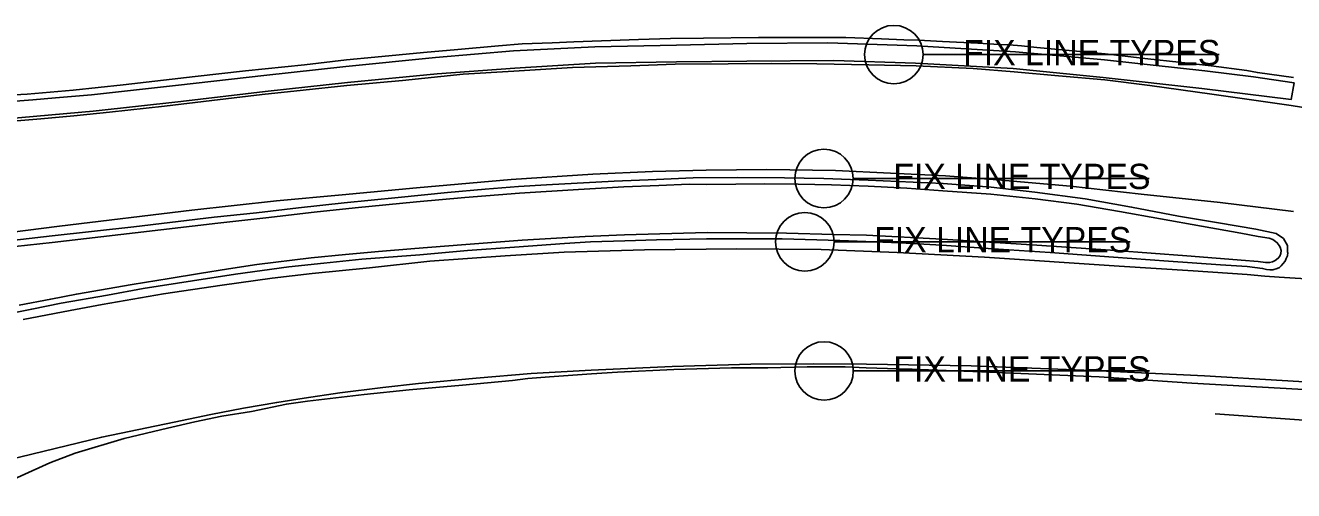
# Model space of a CAD drawing. Extents: x 1659932 to 1663108, y 619867 to 620611.
# Drawn here: x 1660072.9 to 1660213.5, y 620236 to 620287.5 of the extents above; entities that cross this region are included whole.
import ezdxf

# ---------------------------------------------------------------- set-up
doc = ezdxf.new("R2010")
doc.units = 0
for name, color, linetype in [('PM_X_CL_Double_Solid', 7, 'Continuous'), ('PM_X_Lane_Line', 7, 'Continuous'), ('PV_X_Curb', 7, 'Continuous'), ('PV_X_EOP', 7, 'Continuous'), ('RD_X_GR_Lt', 7, 'Continuous'), ('SC_Scratch6', 7, 'Continuous')]:
    doc.layers.add(name, color=color, linetype=linetype)

msp = doc.modelspace()

# ---------------------------------------------------------------- linework, layer by layer
at = {"layer": 'PM_X_CL_Double_Solid'}
msp.add_lwpolyline([(1660345.63, 620252.57), (1660326.3, 620253.2), (1660317.98, 620253.46), (1660304.58, 620253.99), (1660293.85, 620254.51), (1660282.78, 620255.07), (1660272.36, 620255.63), (1660263.03, 620256.2), (1660252.35, 620256.91), (1660236.63, 620258.02), (1660227.99, 620258.63), (1660211.88, 620259.64)], dxfattribs=at)
at = {"layer": 'PM_X_Lane_Line'}
for points in [[(1660220.57, 620277.48), (1660213.23, 620278.66), (1660204.42, 620279.91), (1660197.57, 620280.86), (1660192.56, 620281.48), (1660187.43, 620281.94), (1660182.52, 620282.36), (1660177.98, 620282.73), (1660171.66, 620283.04), (1660166.4, 620283.16), (1660160.63, 620283.25), (1660155.64, 620283.31), (1660150.81, 620283.26), (1660144.95, 620283.21), (1660140.02, 620283.05), (1660133.55, 620282.84), (1660127.08, 620282.43), (1660121.44, 620282.1), (1660114.73, 620281.43), (1660108.54, 620280.86), (1660103.72, 620280.33), (1660099.18, 620279.85), (1660093.58, 620279.19), (1660088.35, 620278.57), (1660082.26, 620277.89), (1660078.29, 620277.51), (1660074.65, 620277.16), (1660071.11, 620276.87)], [(1660213.49, 620266.92), (1660205.36, 620267.91), (1660196.6, 620268.82), (1660188.78, 620269.71), (1660180.66, 620270.42), (1660174.89, 620270.87), (1660162.71, 620271.46), (1660155.11, 620271.55), (1660148.39, 620271.5), (1660142.45, 620271.33), (1660135.83, 620271.03), (1660126.77, 620270.44), (1660116.26, 620269.53), (1660108.04, 620268.76), (1660100.75, 620268.07), (1660091.39, 620267.06), (1660076.7, 620265.28), (1660067.7, 620264.15)], [(1660211.88, 620259.64), (1660210.3, 620259.74), (1660208.35, 620259.94), (1660202.36, 620260.32), (1660194.17, 620260.83), (1660179.22, 620261.83), (1660169.55, 620262.37), (1660161.11, 620262.71), (1660151.78, 620262.75), (1660141.54, 620262.65), (1660132.63, 620262.4), (1660126.11, 620262.01), (1660117.74, 620261.4), (1660111.08, 620260.67), (1660104.71, 620260.03), (1660100.29, 620259.51), (1660094.72, 620258.76), (1660088.23, 620257.77), (1660081.42, 620256.6), (1660077.9, 620255.93), (1660072.69, 620254.93)], [(1660220.84, 620247.68), (1660203.63, 620248.69), (1660191.19, 620249.3), (1660177.76, 620249.8), (1660166.15, 620250.01), (1660160.33, 620250.02), (1660153.33, 620249.99), (1660144.62, 620249.74), (1660135.64, 620249.34), (1660128.98, 620248.97), (1660122.9, 620248.46), (1660116.49, 620247.86), (1660112.55, 620247.42), (1660107.77, 620246.8), (1660103.82, 620246.23), (1660100.78, 620245.75), (1660097.1, 620245.11), (1660093.49, 620244.43), (1660089.41, 620243.57), (1660081.39, 620241.92), (1660064.47, 620237.81)]]:
    msp.add_lwpolyline(points, dxfattribs=at)
at = {"layer": 'PV_X_Curb'}
for points in [[(1660213.49, 620281.76), (1660209.48, 620282.29), (1660208.29, 620282.53), (1660204.35, 620283.05), (1660200.77, 620283.43), (1660197.34, 620283.8), (1660192.61, 620284.35), (1660185.04, 620285.06), (1660183.33, 620285.24), (1660181.95, 620285.36), (1660180.85, 620285.4), (1660178.5, 620285.54), (1660174.56, 620285.73), (1660171.93, 620285.9), (1660170.3, 620285.93), (1660167.82, 620286.03), (1660163.85, 620286.17), (1660161.17, 620286.19), (1660156.01, 620286.17), (1660154.19, 620286.19), (1660148.1, 620286.11), (1660144.41, 620286.07), (1660140.88, 620285.97), (1660133.71, 620285.69), (1660131.3, 620285.6), (1660127.98, 620285.46), (1660125.37, 620285.24), (1660120.85, 620284.86), (1660117.06, 620284.52), (1660111.66, 620283.99), (1660108.51, 620283.69), (1660103.85, 620283.15), (1660097.33, 620282.49), (1660091.75, 620281.87), (1660083.77, 620280.94), (1660078.24, 620280.35), (1660073.12, 620279.9), (1660069.53, 620279.7)], [(1660213.54, 620281.17), (1660209.03, 620281.82), (1660203.65, 620282.48), (1660192.53, 620283.69), (1660182.67, 620284.6), (1660171.74, 620285.24), (1660161.86, 620285.59), (1660152.9, 620285.52), (1660145.1, 620285.33), (1660136.03, 620285.13), (1660127.04, 620284.7), (1660118.4, 620283.95), (1660108.43, 620282.98), (1660099.34, 620281.96), (1660089.91, 620280.89), (1660080.26, 620279.81), (1660076.27, 620279.49), (1660073.74, 620279.27), (1660071.83, 620279.13)], [(1660212.82, 620262.38), (1660212.81, 620263.12), (1660212.37, 620263.91), (1660211.56, 620264.48), (1660209.29, 620264.93), (1660205.16, 620265.66), (1660200.75, 620266.39), (1660195.54, 620267.39), (1660190.4, 620268.29), (1660184.82, 620269.06), (1660179.98, 620269.6), (1660174.66, 620270), (1660166.34, 620270.36), (1660161.44, 620270.56), (1660157.06, 620270.62), (1660151.83, 620270.67), (1660146.93, 620270.62), (1660142.87, 620270.46), (1660138.18, 620270.25), (1660130.69, 620269.87), (1660127.57, 620269.67), (1660123.9, 620269.36), (1660119.7, 620269.01), (1660114.24, 620268.47), (1660108.25, 620267.87), (1660103.18, 620267.32), (1660098.54, 620266.76), (1660093.86, 620266.27), (1660084.95, 620265.21), (1660075.89, 620264.19), (1660066.28, 620263.11)], [(1660072.24, 620256.54), (1660075.73, 620257.21), (1660078.59, 620257.75), (1660084.77, 620258.83), (1660088.86, 620259.5), (1660092.24, 620260.05), (1660095.45, 620260.56), (1660098.58, 620261.03), (1660104.59, 620261.76), (1660108.41, 620262.15), (1660112.06, 620262.47), (1660116.09, 620262.81), (1660121.25, 620263.22), (1660127.98, 620263.73), (1660134.98, 620264.12), (1660139.34, 620264.33), (1660148.49, 620264.59), (1660157.3, 620264.51), (1660162.5, 620264.36), (1660166.14, 620264.27), (1660174.52, 620263.84), (1660184.48, 620263.21), (1660193.76, 620262.59), (1660201.65, 620261.99), (1660208.16, 620261.48), (1660209.08, 620261.42), (1660209.55, 620261.35), (1660210.36, 620261.24), (1660210.83, 620261.25), (1660211.16, 620261.32), (1660211.46, 620261.47), (1660211.79, 620261.72), (1660211.97, 620261.96), (1660212.08, 620262.26), (1660212.1, 620262.59), (1660212, 620262.97), (1660211.89, 620263.15), (1660211.67, 620263.44), (1660211.5, 620263.57), (1660211.18, 620263.79), (1660210.79, 620263.95), (1660209.58, 620264.12), (1660207.63, 620264.49), (1660203.28, 620265.29), (1660194.2, 620266.9), (1660189.45, 620267.7), (1660184.84, 620268.32), (1660179.92, 620268.84), (1660174.6, 620269.2), (1660170.64, 620269.49), (1660166.35, 620269.7), (1660162.27, 620269.87), (1660158.59, 620269.92), (1660154.88, 620269.96), (1660148.44, 620269.9), (1660146.5, 620269.92), (1660143.14, 620269.78), (1660139.27, 620269.63), (1660134.24, 620269.35), (1660127.7, 620268.95), (1660121.65, 620268.45), (1660116.29, 620267.96), (1660109.49, 620267.31), (1660104.94, 620266.83), (1660099.57, 620266.21), (1660094.27, 620265.61), (1660085.09, 620264.55), (1660075.9, 620263.48), (1660066.29, 620262.44)], [(1660070.47, 620255.46), (1660073.63, 620256.1), (1660076.89, 620256.74), (1660082.04, 620257.65), (1660085.98, 620258.37), (1660091.46, 620259.21), (1660096.21, 620259.96), (1660102.12, 620260.79), (1660106.01, 620261.19), (1660110.21, 620261.62), (1660116.66, 620262.09), (1660121.94, 620262.57), (1660127.14, 620262.94), (1660132.68, 620263.35), (1660135.55, 620263.54), (1660139.35, 620263.66), (1660142.88, 620263.75), (1660148.42, 620263.86), (1660156.8, 620263.88), (1660163.19, 620263.69), (1660169.88, 620263.42), (1660174.5, 620263.18), (1660179.65, 620262.82), (1660186.49, 620262.37), (1660193.54, 620261.86), (1660199.63, 620261.4), (1660205.39, 620260.98), (1660208.33, 620260.8), (1660210.06, 620260.6), (1660210.49, 620260.49), (1660210.86, 620260.44), (1660211.2, 620260.45), (1660211.68, 620260.58), (1660211.94, 620260.7), (1660212.12, 620260.87), (1660212.29, 620261.11), (1660212.54, 620261.41), (1660212.66, 620261.7), (1660212.8, 620261.99), (1660212.84, 620262.38)]]:
    msp.add_lwpolyline(points, dxfattribs=at)
at = {"layer": 'PV_X_EOP'}
for points in [[(1660213.54, 620281.17), (1660213.23, 620279.31), (1660203.33, 620280.54), (1660192.37, 620281.76), (1660182.39, 620282.74), (1660171.6, 620283.34), (1660162.53, 620283.63), (1660152.9, 620283.56), (1660145.11, 620283.48), (1660136.1, 620283.33), (1660127.17, 620282.78), (1660118.55, 620282.14), (1660108.64, 620281.19), (1660099.51, 620280.21), (1660090.16, 620279.07), (1660080.43, 620278.03), (1660070.88, 620277.18)], [(1660226.37, 620246.52), (1660202.2, 620247.87), (1660191.93, 620248.59), (1660178.89, 620249.16), (1660172.05, 620249.39), (1660166.13, 620249.6), (1660163.79, 620249.68), (1660159.56, 620249.68), (1660155.21, 620249.6), (1660151.18, 620249.59), (1660144.79, 620249.42), (1660138.56, 620249.11), (1660135.66, 620248.91), (1660131.02, 620248.58), (1660128.6, 620248.4), (1660126.93, 620248.19), (1660121.36, 620247.66), (1660115.46, 620247.15), (1660110.48, 620246.64), (1660104.19, 620245.9), (1660101.86, 620245.57), (1660098, 620244.76), (1660094.69, 620244.22), (1660091.71, 620243.59), (1660088.69, 620242.91), (1660083.86, 620241.77), (1660078.44, 620240.13), (1660075.63, 620239.07), (1660068.83, 620235.99)]]:
    msp.add_lwpolyline(points, dxfattribs=at)
at = {"layer": 'RD_X_GR_Lt'}
msp.add_line((1660299.33, 620237.69), (1660204.78, 620244.48), dxfattribs=at)
at = {"layer": 'SC_Scratch6'}
for p, q in [((1660172.43, 620284.28), (1660205.23, 620284.28)), ((1660164.69, 620270.56), (1660197.49, 620270.56)), ((1660162.57, 620263.55), (1660195.37, 620263.55)), ((1660164.7, 620249.24), (1660197.5, 620249.24))]:
    msp.add_line(p, q, dxfattribs=at)
for centre in [(1660169.18, 620284.28), (1660161.44, 620270.56), (1660159.32, 620263.55), (1660161.45, 620249.24)]:
    msp.add_circle(centre, 3.24, dxfattribs=at)

# ---------------------------------------------------------------- texts
for p in [(1660176.86, 620283.11), (1660169.12, 620269.39), (1660167, 620262.38), (1660169.13, 620248.07)]:
    msp.add_text('FIX LINE TYPES', height=2.8, dxfattribs=at).set_placement(p)

doc.saveas('drawing.dxf')
